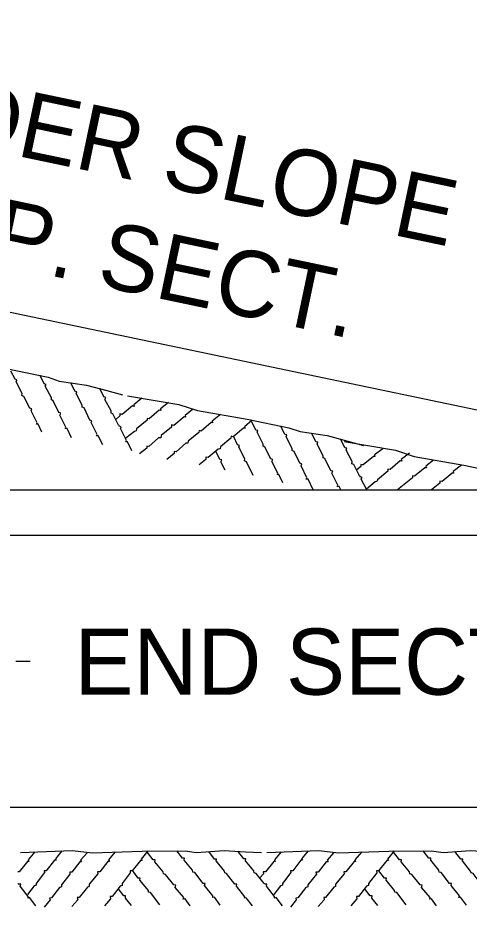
# Model space of a CAD drawing. Extents: x 49991.4 to 50021, y 49987.6 to 50011.4.
# Drawn here: x 50014.291 to 50014.7, y 49997.164 to 49997.97 of the extents above; entities that cross this region are included whole.
import ezdxf

# ---------------------------------------------------------------- set-up
doc = ezdxf.new("R2010")
doc.units = 0
for name, color, linetype in [('Level 1', 7, 'Continuous'), ('Level 2', 7, 'Continuous'), ('Level 3', 7, 'Continuous'), ('Level 4', 7, 'Continuous')]:
    doc.layers.add(name, color=color, linetype=linetype)

msp = doc.modelspace()

# ---------------------------------------------------------------- linework, layer by layer
at = {"layer": 'Level 1'}
msp.add_line((50012.6493, 49997.5423), (50014.7997, 49997.5423), dxfattribs=at)
for points in [[(50014.1716, 49997.6736), (50014.2181, 49997.6658), (50014.2352, 49997.6601), (50014.2802, 49997.6523), (50014.318, 49997.6446), (50014.328, 49997.641), (50014.3528, 49997.6374), (50014.3714, 49997.6325), (50014.3856, 49997.6286)], [(50014.3124, 49997.5947), (50014.309, 49997.602), (50014.3075, 49997.6019), (50014.308, 49997.6031), (50014.3026, 49997.6139), (50014.3033, 49997.6157), (50014.3016, 49997.6163), (50014.2961, 49997.6271), (50014.2944, 49997.628), (50014.2946, 49997.6298), (50014.2892, 49997.6403), (50014.2898, 49997.642), (50014.2882, 49997.6426), (50014.2844, 49997.65)], [(50014.3393, 49997.5896), (50014.3354, 49997.598), (50014.3336, 49997.598), (50014.3342, 49997.5992), (50014.3288, 49997.61), (50014.3297, 49997.6118), (50014.3279, 49997.6124), (50014.3225, 49997.6232), (50014.321, 49997.624), (50014.321, 49997.6259), (50014.3154, 49997.6364), (50014.3162, 49997.638), (50014.3144, 49997.6386), (50014.3108, 49997.6462)], [(50014.3675, 49997.5832), (50014.3633, 49997.5914), (50014.3618, 49997.5914), (50014.3624, 49997.5926), (50014.357, 49997.6034), (50014.3576, 49997.605), (50014.356, 49997.6056), (50014.3506, 49997.6166), (50014.3489, 49997.6175), (50014.349, 49997.6192), (50014.3436, 49997.6298), (50014.3441, 49997.6314), (50014.3424, 49997.6319), (50014.3387, 49997.6394)], [(50014.3819, 49997.601), (50014.3768, 49997.6112), (50014.3752, 49997.612), (50014.3753, 49997.6139), (50014.3696, 49997.6244), (50014.3705, 49997.626), (50014.3686, 49997.6266), (50014.3648, 49997.6343)], [(50014.4029, 49997.6256), (50014.3956, 49997.6196), (50014.396, 49997.6181), (50014.3945, 49997.6186), (50014.3852, 49997.6106), (50014.3843, 49997.611)], [(50014.39, 49997.6277), (50014.4365, 49997.6199), (50014.4534, 49997.6142), (50014.4984, 49997.6064), (50014.5361, 49997.5986), (50014.5463, 49997.5952), (50014.571, 49997.5917), (50014.5896, 49997.5864), (50014.6039, 49997.5827)], [(50014.4272, 49997.6216), (50014.42, 49997.6157), (50014.4203, 49997.6142), (50014.4188, 49997.6145), (50014.4096, 49997.6067), (50014.4077, 49997.6072), (50014.4077, 49997.6055), (50014.3981, 49997.5976), (50014.3978, 49997.5959), (50014.3962, 49997.5954), (50014.3886, 49997.5892)], [(50014.3842, 49997.611), (50014.3831, 49997.6112), (50014.3831, 49997.6094), (50014.3796, 49997.6066)], [(50014.449, 49997.6151), (50014.4422, 49997.6097), (50014.4426, 49997.6082), (50014.4412, 49997.6085), (50014.432, 49997.6007), (50014.43, 49997.6012), (50014.4299, 49997.5992), (50014.4204, 49997.5916), (50014.4202, 49997.5896), (50014.4182, 49997.5894), (50014.4092, 49997.5818), (50014.4074, 49997.582), (50014.4074, 49997.5802), (50014.4008, 49997.5749)], [(50014.4743, 49997.6106), (50014.4668, 49997.6046), (50014.4671, 49997.6031), (50014.4659, 49997.6036), (50014.4566, 49997.5956), (50014.4548, 49997.5962), (50014.4546, 49997.5944), (50014.445, 49997.5864), (50014.4446, 49997.5848), (50014.443, 49997.5846), (50014.434, 49997.5767), (50014.4322, 49997.5772), (50014.4322, 49997.5752), (50014.4256, 49997.57)], [(50014.3939, 49997.5779), (50014.39, 49997.586), (50014.3885, 49997.586), (50014.389, 49997.5872), (50014.3836, 49997.598), (50014.3843, 49997.5996), (50014.3826, 49997.6001), (50014.3822, 49997.601)], [(50014.5031, 49997.6055), (50014.496, 49997.5996), (50014.4965, 49997.5982), (50014.495, 49997.5983), (50014.4857, 49997.5906), (50014.4839, 49997.591), (50014.4836, 49997.5892), (50014.4743, 49997.5815), (50014.474, 49997.5796), (50014.4722, 49997.5794), (50014.463, 49997.5716), (50014.4611, 49997.5719), (50014.4611, 49997.57), (50014.4548, 49997.565)], [(50014.5307, 49997.5488), (50014.5271, 49997.5562), (50014.5256, 49997.5562), (50014.5262, 49997.5575), (50014.5208, 49997.5682), (50014.5217, 49997.5698), (50014.5199, 49997.5704), (50014.5145, 49997.5812), (50014.513, 49997.5821), (50014.513, 49997.5839), (50014.5074, 49997.5946), (50014.508, 49997.5962), (50014.5064, 49997.5966), (50014.5026, 49997.6042)], [(50014.5583, 49997.5423), (50014.5536, 49997.5521), (50014.552, 49997.5521), (50014.5524, 49997.5533), (50014.5472, 49997.5641), (50014.548, 49997.5659), (50014.5462, 49997.5665), (50014.5409, 49997.5773), (50014.5391, 49997.578), (50014.5391, 49997.58), (50014.5337, 49997.5905), (50014.5344, 49997.5923), (50014.5326, 49997.5926), (50014.529, 49997.6001)], [(50014.5832, 49997.5423), (50014.5817, 49997.5455), (50014.58, 49997.5455), (50014.5806, 49997.5467), (50014.5751, 49997.5575), (50014.576, 49997.5593), (50014.5742, 49997.5596), (50014.5688, 49997.5707), (50014.5673, 49997.5714), (50014.5673, 49997.5731), (50014.5619, 49997.5839), (50014.5626, 49997.5856), (50014.5607, 49997.586), (50014.5571, 49997.5935)], [(50014.504, 49997.5554), (50014.4977, 49997.5677), (50014.496, 49997.5686), (50014.4962, 49997.5704), (50014.4908, 49997.581), (50014.4914, 49997.5827), (50014.4896, 49997.5832), (50014.4862, 49997.5905)], [(50014.6002, 49997.555), (50014.595, 49997.5653), (50014.5934, 49997.566), (50014.5936, 49997.568), (50014.5882, 49997.5785), (50014.5886, 49997.5802), (50014.5868, 49997.5806), (50014.583, 49997.5886)], [(50014.5862, 49997.5861), (50014.6327, 49997.5783), (50014.6498, 49997.5726), (50014.6948, 49997.5648), (50014.7326, 49997.557), (50014.7427, 49997.5534), (50014.7674, 49997.5501), (50014.786, 49997.5449), (50014.8003, 49997.5411)], [(50014.4786, 49997.5602), (50014.4746, 49997.5677), (50014.4755, 49997.5695), (50014.4736, 49997.57), (50014.47, 49997.5774)], [(50014.6212, 49997.5797), (50014.6138, 49997.574), (50014.6141, 49997.5725), (50014.6129, 49997.5726), (50014.6034, 49997.565), (50014.6026, 49997.5652)], [(50014.6454, 49997.5756), (50014.6381, 49997.5698), (50014.6386, 49997.5683), (50014.6372, 49997.5686), (50014.6279, 49997.5608), (50014.626, 49997.5611), (50014.626, 49997.5594), (50014.6165, 49997.5516), (50014.616, 49997.55), (50014.6144, 49997.5496), (50014.6066, 49997.5431)], [(50014.6672, 49997.5692), (50014.6604, 49997.5638), (50014.6609, 49997.5623), (50014.6594, 49997.5624), (50014.6501, 49997.5548), (50014.6483, 49997.5551), (50014.6482, 49997.5534), (50014.6347, 49997.5423)], [(50014.6024, 49997.5652), (50014.6015, 49997.5653), (50014.6015, 49997.5635), (50014.5979, 49997.5606)], [(50014.6926, 49997.5647), (50014.685, 49997.559), (50014.6855, 49997.5575), (50014.6842, 49997.5576), (50014.675, 49997.55), (50014.673, 49997.5503), (50014.6729, 49997.5485), (50014.6653, 49997.5423)], [(50014.6067, 49997.5423), (50014.6018, 49997.552), (50014.6026, 49997.5536), (50014.6009, 49997.5542), (50014.6004, 49997.555)], [(50014.3059, 49997.2141), (50014.2999, 49997.207), (50014.3007, 49997.2055), (50014.2993, 49997.2055), (50014.2919, 49997.1959), (50014.2907, 49997.1959)], [(50014.2929, 49997.2135), (50014.3401, 49997.2154), (50014.3579, 49997.2133), (50014.4033, 49997.2148), (50014.4421, 49997.2151), (50014.4525, 49997.2136), (50014.4777, 49997.2154), (50014.4968, 49997.2142), (50014.5113, 49997.2135)], [(50014.3305, 49997.2149), (50014.3247, 49997.2079), (50014.3253, 49997.2065), (50014.3239, 49997.2065), (50014.3163, 49997.1969), (50014.3145, 49997.1969), (50014.3147, 49997.1953), (50014.3071, 49997.1855), (50014.3071, 49997.1839), (50014.3054, 49997.1833), (50014.2994, 49997.1755)], [(50014.3789, 49997.2141), (50014.3729, 49997.207), (50014.3737, 49997.2055), (50014.3721, 49997.2055), (50014.3648, 49997.1959), (50014.3627, 49997.1959), (50014.3631, 49997.1941), (50014.3553, 49997.1847), (50014.3553, 49997.1827), (50014.3537, 49997.1821), (50014.3463, 49997.1727), (50014.3445, 49997.1727), (50014.3449, 49997.1707), (50014.3397, 49997.1644)], [(50014.4083, 49997.2149), (50014.4025, 49997.2076), (50014.4032, 49997.2064), (50014.4017, 49997.2064), (50014.3942, 49997.1968), (50014.3924, 49997.1968), (50014.3925, 49997.1951), (50014.3851, 49997.1855), (50014.3851, 49997.1836), (50014.3834, 49997.1831), (50014.3761, 49997.1737), (50014.3743, 49997.1735), (50014.3745, 49997.1716), (50014.3693, 49997.1653)], [(50014.4469, 49997.1653), (50014.4421, 49997.1716), (50014.4405, 49997.1713), (50014.4409, 49997.1727), (50014.4332, 49997.1819), (50014.4338, 49997.1839), (50014.4319, 49997.1841), (50014.4243, 49997.1937), (50014.4225, 49997.1941), (50014.4224, 49997.1959), (50014.4149, 49997.2051), (50014.4151, 49997.207), (50014.4134, 49997.207), (50014.4081, 49997.2135)], [(50014.4741, 49997.1659), (50014.4687, 49997.1731), (50014.4673, 49997.1728), (50014.4674, 49997.1741), (50014.4599, 49997.1835), (50014.4603, 49997.1854), (50014.4585, 49997.1855), (50014.4509, 49997.1953), (50014.4493, 49997.1956), (50014.4489, 49997.1974), (50014.4413, 49997.2065), (50014.4417, 49997.2085), (50014.4398, 49997.2085), (50014.4347, 49997.2149)], [(50014.5033, 49997.1651), (50014.4975, 49997.1725), (50014.4961, 49997.1721), (50014.4962, 49997.1734), (50014.4887, 49997.183), (50014.4891, 49997.1847), (50014.4873, 49997.1849), (50014.4797, 49997.1945), (50014.4781, 49997.195), (50014.4779, 49997.1967), (50014.4703, 49997.2059), (50014.4705, 49997.2076), (50014.4687, 49997.2076), (50014.4637, 49997.2145)], [(50014.5137, 49997.1855), (50014.5065, 49997.1945), (50014.5047, 49997.1951), (50014.5045, 49997.1968), (50014.4969, 49997.2059), (50014.4973, 49997.2079), (50014.4955, 49997.2079), (50014.4901, 49997.2148)], [(50014.5292, 49997.2141), (50014.5232, 49997.207), (50014.5238, 49997.2055), (50014.5225, 49997.2055), (50014.5149, 49997.1959), (50014.5141, 49997.1959)], [(50014.5163, 49997.2135), (50014.5634, 49997.2154), (50014.5813, 49997.2133), (50014.6267, 49997.2148), (50014.6653, 49997.2151), (50014.6759, 49997.2136), (50014.7008, 49997.2154), (50014.7201, 49997.2142), (50014.7347, 49997.2135)], [(50014.5538, 49997.2149), (50014.5478, 49997.2079), (50014.5485, 49997.2065), (50014.5471, 49997.2065), (50014.5397, 49997.1969), (50014.5377, 49997.1969), (50014.5381, 49997.1953), (50014.5304, 49997.1855), (50014.5304, 49997.1839), (50014.5287, 49997.1833), (50014.5227, 49997.1755)], [(50014.6023, 49997.2141), (50014.5959, 49997.207), (50014.5967, 49997.2055), (50014.5953, 49997.2055), (50014.5879, 49997.1959), (50014.5861, 49997.1959), (50014.5862, 49997.1941), (50014.5785, 49997.1847), (50014.5785, 49997.1827), (50014.5769, 49997.1821), (50014.5695, 49997.1727), (50014.5679, 49997.1727), (50014.5682, 49997.1707), (50014.5628, 49997.1644)], [(50014.6317, 49997.2149), (50014.6257, 49997.2076), (50014.6264, 49997.2064), (50014.6251, 49997.2064), (50014.6175, 49997.1968), (50014.6157, 49997.1968), (50014.6159, 49997.1951), (50014.6083, 49997.1855), (50014.6083, 49997.1836), (50014.6065, 49997.1831), (50014.5993, 49997.1737), (50014.5975, 49997.1735), (50014.5977, 49997.1716), (50014.5923, 49997.1653)], [(50014.6701, 49997.1653), (50014.6654, 49997.1716), (50014.6639, 49997.1713), (50014.6641, 49997.1727), (50014.6565, 49997.1819), (50014.6569, 49997.1839), (50014.6551, 49997.1841), (50014.6475, 49997.1937), (50014.6459, 49997.1941), (50014.6455, 49997.1959), (50014.6379, 49997.2051), (50014.6384, 49997.207), (50014.6365, 49997.207), (50014.6313, 49997.2135)], [(50014.6973, 49997.1659), (50014.6918, 49997.1731), (50014.6903, 49997.1728), (50014.6907, 49997.1741), (50014.6833, 49997.1835), (50014.6835, 49997.1854), (50014.6817, 49997.1855), (50014.6743, 49997.1953), (50014.6725, 49997.1956), (50014.6721, 49997.1974), (50014.6647, 49997.2065), (50014.6648, 49997.2085), (50014.6631, 49997.2085), (50014.6579, 49997.2149)], [(50014.7263, 49997.1651), (50014.7207, 49997.1725), (50014.7193, 49997.1721), (50014.7195, 49997.1734), (50014.7119, 49997.183), (50014.7123, 49997.1847), (50014.7105, 49997.1849), (50014.7031, 49997.1945), (50014.7013, 49997.195), (50014.7009, 49997.1967), (50014.6935, 49997.2059), (50014.6939, 49997.2076), (50014.6919, 49997.2076), (50014.6867, 49997.2145)], [(50014.3533, 49997.2133), (50014.3475, 49997.2065), (50014.3483, 49997.2052), (50014.3469, 49997.2052), (50014.3395, 49997.1956), (50014.3377, 49997.1956), (50014.3378, 49997.1939), (50014.3301, 49997.1842), (50014.3301, 49997.1825), (50014.3283, 49997.1818), (50014.3211, 49997.1725), (50014.3193, 49997.1722), (50014.3198, 49997.1705), (50014.3144, 49997.1639)], [(50014.5765, 49997.2133), (50014.5709, 49997.2065), (50014.5717, 49997.2052), (50014.5701, 49997.2052), (50014.5627, 49997.1956), (50014.5607, 49997.1956), (50014.5611, 49997.1939), (50014.5533, 49997.1842), (50014.5533, 49997.1825), (50014.5517, 49997.1818), (50014.5443, 49997.1725), (50014.5425, 49997.1722), (50014.5429, 49997.1705), (50014.5377, 49997.1639)], [(50014.4194, 49997.1661), (50014.4107, 49997.1771), (50014.4091, 49997.1775), (50014.4089, 49997.1791), (50014.4013, 49997.1884), (50014.4015, 49997.1902), (50014.3997, 49997.1902), (50014.3947, 49997.1968)], [(50014.5139, 49997.1959), (50014.5129, 49997.1959), (50014.5131, 49997.1941), (50014.5103, 49997.1907)], [(50014.6425, 49997.1661), (50014.6341, 49997.1771), (50014.6323, 49997.1775), (50014.6319, 49997.1791), (50014.6245, 49997.1884), (50014.6247, 49997.1902), (50014.6228, 49997.1902), (50014.6177, 49997.1968)], [(50014.3069, 49997.1653), (50014.3013, 49997.1727), (50014.2999, 49997.1722), (50014.3001, 49997.1735), (50014.2927, 49997.183), (50014.2933, 49997.1848), (50014.2913, 49997.1849), (50014.2907, 49997.1855)], [(50014.5303, 49997.1653), (50014.5247, 49997.1727), (50014.5231, 49997.1722), (50014.5233, 49997.1735), (50014.5159, 49997.183), (50014.5163, 49997.1848), (50014.5143, 49997.1849), (50014.5141, 49997.1855)], [(50014.3937, 49997.1656), (50014.3882, 49997.1722), (50014.3883, 49997.1741), (50014.3867, 49997.1741), (50014.3815, 49997.1809)], [(50014.6168, 49997.1656), (50014.6114, 49997.1722), (50014.6117, 49997.1741), (50014.6099, 49997.1741), (50014.6048, 49997.1809)]]:
    msp.add_lwpolyline(points, dxfattribs=at)
at = {"layer": 'Level 3'}
for p, q in [((50013.83176, 49997.79821), (50014.8104, 49997.59312)), ((50014.3019, 49997.3866), (50014.2888, 49997.3866))]:
    msp.add_line(p, q, dxfattribs=at)
at = {"layer": 'Level 4'}
for p, q in [((50012.6493, 49997.5013), (50014.8057, 49997.5013)), ((50012.6493, 49997.2547), (50015.1696, 49997.2547))]:
    msp.add_line(p, q, dxfattribs=at)

# ---------------------------------------------------------------- texts
at = {"layer": 'Level 2'}
for s, p in [('SHOULDER SLOPE', (50013.96092, 49997.91438)), ('SEE TYP. SECT.', (50013.98548, 49997.80703))]:
    msp.add_text(s, height=0.06, rotation=348.12367, dxfattribs=at).set_placement(p)
msp.add_text('END SECTION', height=0.06, dxfattribs=at).set_placement((50014.3419, 49997.3566))

doc.saveas('drawing.dxf')
